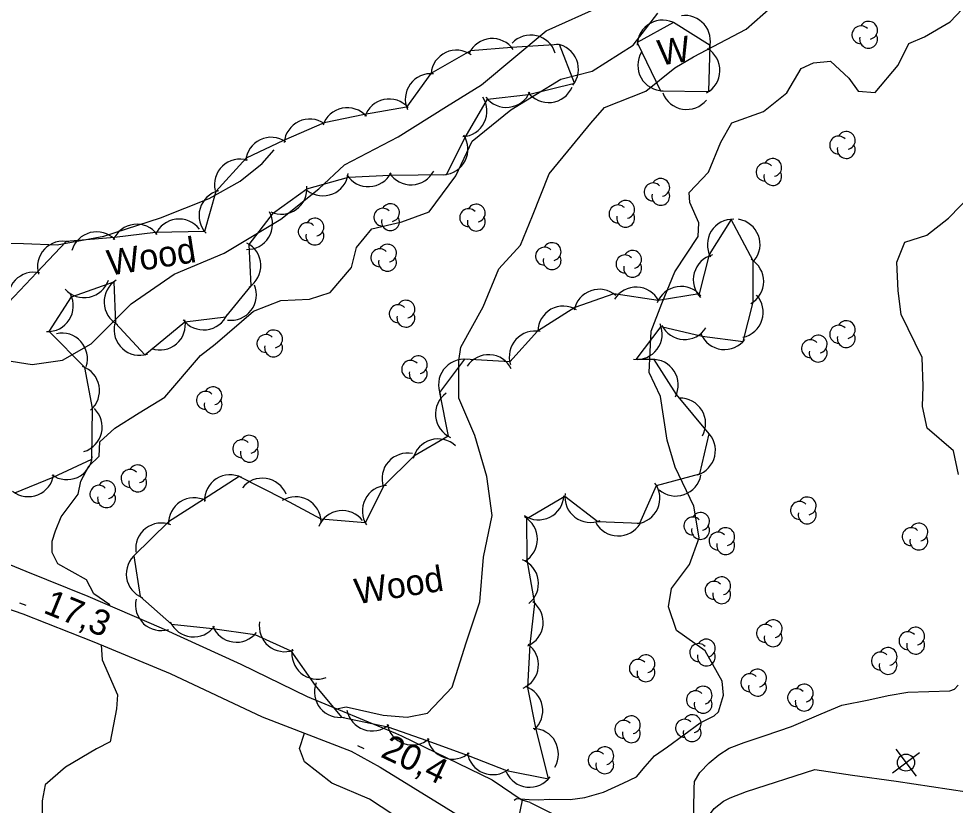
# Model space of a CAD drawing. Extents: x 646142 to 649934, y 5874075 to 5876351.
# Drawn here: x 647010.1 to 647120, y 5874901.2 to 5874993.5 of the extents above; entities that cross this region are included whole.
import ezdxf

# ---------------------------------------------------------------- set-up
doc = ezdxf.new("R2010")
doc.units = 0
for name, color, linetype in [('Niveau 1', 7, 'Continuous'), ('Niveau 19', 7, 'Continuous'), ('Niveau 2', 7, 'Continuous'), ('Niveau 3', 7, 'Continuous'), ('Niveau 36', 7, 'Continuous'), ('Niveau 4', 7, 'Continuous'), ('Niveau 44', 7, 'Continuous'), ('Niveau 52', 7, 'Continuous')]:
    doc.layers.add(name, color=color, linetype=linetype)

msp = doc.modelspace()

# ---------------------------------------------------------------- linework, layer by layer
at = {"layer": 'Niveau 1'}
for points in [[(647047.41, 5874912.5), (647048.53, 5874912.71), (647052.87, 5874911.75), (647055.68, 5874911.51), (647058.08, 5874911.98), (647060.97, 5874915.04), (647062.61, 5874920.22), (647064.23, 5874925.06), (647064.64, 5874930.3), (647065.68, 5874935.19), (647065.05, 5874939.75), (647063.65, 5874944.58), (647061.77, 5874948.95), (647061.75, 5874953.34), (647062, 5874954.92), (647064.61, 5874959.68), (647066.44, 5874964.13), (647069.01, 5874966.92), (647070.41, 5874970.35), (647072.37, 5874975.27), (647075.12, 5874978.6), (647077.24, 5874981.23), (647078.86, 5874983.07), (647083.72, 5874984.99), (647087.11, 5874987.74), (647089.31, 5874989), (647095.49, 5874992.26), (647098.42, 5874994.86)], [(647062.19, 5874853.88), (647063.16, 5874855.88), (647062.71, 5874856.94), (647061.06, 5874857.7), (647059.61, 5874860.1), (647058.71, 5874862.15), (647056.52, 5874864.37), (647056.19, 5874865.95), (647056.75, 5874868.55), (647057.24, 5874872.42), (647056.15, 5874875.84), (647054.13, 5874878.64), (647053.57, 5874880.79), (647053.96, 5874883.43), (647054, 5874888.29), (647054.75, 5874891.89), (647056.92, 5874895.91), (647057.02, 5874897.25), (647055.38, 5874899.17), (647051.28, 5874901.89), (647046.85, 5874903.76), (647043.64, 5874906.28), (647043.08, 5874907.84), (647043.63, 5874909.64)]]:
    msp.add_lwpolyline(points, dxfattribs=at)
at = {"layer": 'Niveau 19'}
for points in [[(646956.64, 5874982.64), (646957.27, 5874973.6), (646958.12, 5874968.89), (646958.69, 5874963.46), (646959.08, 5874961.51), (646960.28, 5874959.62), (646963.28, 5874955.54), (646968.34, 5874950.23), (646973.77, 5874946.12), (646979.55, 5874941.91), (646985.8, 5874939.02), (646993.5, 5874935.43), (647000.66, 5874932.62), (647004.71, 5874931.19), (647010.93, 5874928.65), (647018.21, 5874925.73), (647026.82, 5874921.99), (647036.17, 5874917.73), (647043.97, 5874913.93), (647054.34, 5874909.64), (647055.05, 5874909.32), (647065.67, 5874904.14), (647069.18, 5874901.78)], [(646938.02, 5874920.39), (646945.32, 5874923.5), (646951.28, 5874926.75), (646958.94, 5874929.59), (646963.33, 5874931.22), (646969.44, 5874933.03), (646979.24, 5874933.97), (646982.52, 5874934.12), (646984.51, 5874933.75), (646985.91, 5874933.31), (646990.94, 5874930.74), (646995.74, 5874928.53), (647002.07, 5874926.12), (647005.59, 5874925.34), (647010.58, 5874923.64), (647018.93, 5874920.34), (647027.89, 5874916.63), (647038.67, 5874911.56), (647049.14, 5874907.5), (647052.53, 5874905.64), (647068.02, 5874896.1)]]:
    msp.add_lwpolyline(points, dxfattribs=at)
at = {"layer": 'Niveau 2'}
for points in [[(647008.48, 5874953.4), (647011.67, 5874952.9), (647015.23, 5874953.43), (647018.6, 5874955.33), (647023.32, 5874960.02), (647028.34, 5874963.52), (647034.22, 5874965.96), (647040.87, 5874969.97), (647045.35, 5874973.54), (647048.34, 5874976.32), (647054.66, 5874979.61), (647060.31, 5874983.18), (647064.42, 5874985.72), (647072.01, 5874992.08), (647078.48, 5874994.98), (647085.23, 5874998.54), (647090.86, 5875001.06), (647095.93, 5875004.05), (647102.07, 5875006.74), (647108.2, 5875008.27), (647114.93, 5875011.48), (647118.07, 5875014.51)], [(647068.26, 5874901.76), (647068.52, 5874901.97), (647070.03, 5874901.84), (647071.1, 5874901.8), (647072.4, 5874901.89), (647074.81, 5874901.86), (647076.53, 5874902.09), (647078.73, 5874902.71), (647081.04, 5874903.77), (647082.6, 5874904.51), (647083.63, 5874905.73), (647084.71, 5874906.96), (647086.24, 5874908.04), (647090.09, 5874910.86), (647091.74, 5874911.66), (647092.22, 5874912.15), (647092.82, 5874914.08), (647092.66, 5874915.73), (647090.69, 5874919.29), (647087.32, 5874921.67), (647086.35, 5874924.45), (647086.72, 5874926.62), (647088.82, 5874929.43), (647089.96, 5874932.54), (647089.36, 5874936.28), (647087.17, 5874940.85), (647086.22, 5874944.04), (647085.43, 5874949.15), (647084.11, 5874951.96), (647084.33, 5874956.82), (647085.58, 5874960.06), (647087.12, 5874963.78), (647089.85, 5874967.91), (647089.92, 5874969.53), (647088.87, 5874971.9), (647088.81, 5874973.11), (647091.07, 5874975.46), (647092.52, 5874979), (647093.81, 5874981.26), (647097.5, 5874982.6), (647100.24, 5874984.78), (647101.93, 5874987.65), (647103.37, 5874988.31), (647105.38, 5874988.51), (647107.55, 5874986.53), (647108.63, 5874984.97), (647110.61, 5874984.82), (647113.31, 5874988.03), (647114.57, 5874990.57), (647116.4, 5874991.38), (647119.42, 5874993.12), (647122.93, 5874996.86)], [(647020.78, 5874924.61), (647020.8, 5874924.68), (647018.92, 5874925.99), (647018.07, 5874927.64), (647014.69, 5874929.51), (647014.03, 5874930.83), (647014.02, 5874932.16), (647014.43, 5874933.36), (647015.08, 5874935.04), (647017.09, 5874937.67), (647017.41, 5874939.2), (647018.34, 5874940.97), (647019.56, 5874942.13), (647019.63, 5874943.82), (647021.39, 5874945.43), (647024.24, 5874947.22), (647027.26, 5874949.08), (647031.44, 5874953.94), (647033.17, 5874955.27), (647037.67, 5874959.18), (647040.86, 5874960.42), (647044.22, 5874960.58), (647046.65, 5874961.34), (647049.15, 5874964.3), (647049.74, 5874966.62), (647051.56, 5874968.82), (647055.08, 5874969.63), (647058.28, 5874970.81), (647061.41, 5874975.05), (647063.34, 5874979.11), (647067.86, 5874982.79), (647073.73, 5874986.38), (647077.42, 5874987.32), (647082.23, 5874990.39), (647085.12, 5874994.14)], [(647120.39, 5874939.98), (647119.83, 5874942.75), (647116.72, 5874945.43), (647116.18, 5874947.97), (647116.24, 5874950.34), (647116.14, 5874953.72), (647113.67, 5874958.77), (647113.34, 5874961.56), (647113.18, 5874964.93), (647114.11, 5874967.27), (647116.69, 5874968.1), (647119.21, 5874970.07), (647123.36, 5874974.34)], [(647019.79, 5874919.99), (647019.91, 5874918.23), (647021.71, 5874914.12), (647021.58, 5874912.49), (647020.85, 5874908.6), (647019.24, 5874907.8), (647015.61, 5874905.65), (647013.2, 5874903.56), (647012.86, 5874901.68), (647012.88, 5874899.02)], [(647090.87, 5874896.34), (647089.8, 5874896.81), (647089.51, 5874897.35), (647089.35, 5874898.4), (647089.34, 5874900.76), (647089.37, 5874903.13), (647089.43, 5874903.96), (647090.04, 5874905.03), (647091.13, 5874906.16), (647092.28, 5874907.1), (647093.5, 5874907.86), (647095.26, 5874908.53), (647097.73, 5874909.37), (647100.8, 5874910.41), (647104.27, 5874911.89), (647106.71, 5874912.92), (647109.88, 5874913.54), (647112.14, 5874914.07), (647114.46, 5874914.46), (647119.37, 5874914.59), (647119.92, 5874914.79), (647120.36, 5874915.27)]]:
    msp.add_lwpolyline(points, dxfattribs=at)
at = {"layer": 'Niveau 3'}
for p, q in [((647010.22, 5874924.94), (647010.96, 5874924.64)), ((647049.88, 5874908.18), (647050.6, 5874907.83))]:
    msp.add_line(p, q, dxfattribs=at)
at = {"layer": 'Niveau 36'}
for p, q in [((647113.03, 5874907.77), (647115.43, 5874904.58)), ((647112.64, 5874904.98), (647115.83, 5874907.37))]:
    msp.add_line(p, q, dxfattribs=at)
msp.add_circle((647114.24, 5874906.17), 1, dxfattribs=at)
at = {"layer": 'Niveau 4'}
msp.add_lwpolyline([(646977.28, 5874967.68), (646980.23, 5874968.49), (646982.34, 5874968.18), (646984.21, 5874966.58), (646985.87, 5874966.13), (646990.46, 5874966.6), (646999.03, 5874967.96), (647004.2, 5874968.47), (647007.08, 5874967.18), (647010.68, 5874967.11), (647014.63, 5874966.95), (647020.1, 5874967.96), (647026.75, 5874970.1), (647032.45, 5874972.4), (647036.1, 5874974.43), (647038.7, 5874976.49), (647040.07, 5874978.11)], dxfattribs=at)
at = {"layer": 'Niveau 44'}
for points in [[(647086.95, 5874993.04), (647082.71, 5874990.68), (647085.42, 5874985.04), (647091.1, 5874984.94), (647091.24, 5874990.34), (647086.95, 5874993.04)], [(647013.7, 5874956.77), (647016.32, 5874960.85), (647021.28, 5874962.6), (647021.45, 5874957.75), (647024.91, 5874954.04), (647029.61, 5874957.92), (647034.43, 5874958.5), (647037.4, 5874962.15), (647037.16, 5874967), (647040, 5874970.69), (647043.94, 5874973.52), (647048.8, 5874974.91), (647053.65, 5874975.12), (647060.31, 5874975.21), (647062.49, 5874979.55), (647065.13, 5874984.04), (647069.95, 5874984.6), (647075.33, 5874985.93), (647073.56, 5874990.45), (647067.96, 5874990.12), (647063.12, 5874989.72), (647058.48, 5874987.04), (647055.63, 5874983.11), (647050.69, 5874982.26), (647045.94, 5874981.27), (647041.18, 5874979.2), (647036.79, 5874977.12), (647033.26, 5874973.19), (647031.9, 5874968.53), (647026.16, 5874968.41), (647021.35, 5874967.81), (647015.69, 5874967.34), (647012.25, 5874963.71), (647008.92, 5874960.18)], [(647082.58, 5874953.49), (647085.49, 5874957.38), (647090.32, 5874956.21), (647095.14, 5874955.62), (647096.29, 5874960.23), (647096.31, 5874965.08), (647093.72, 5874969.94), (647091.15, 5874965.82), (647089.96, 5874961.18), (647085.17, 5874960.42), (647079.96, 5874961.2), (647075.38, 5874959.58), (647071.01, 5874956.81), (647067.74, 5874953.22), (647062.41, 5874953.51), (647059.51, 5874949.62), (647060.5, 5874944.49), (647056.48, 5874942.15), (647052.96, 5874938.67), (647050.77, 5874934.33), (647045.59, 5874934.76), (647041.32, 5874937.07), (647036, 5874939.75), (647031.79, 5874937.06), (647027.7, 5874934.44), (647023.63, 5874930.46), (647024.35, 5874925.66), (647028.05, 5874922.43), (647032.87, 5874921.92), (647037.81, 5874921.2), (647042.06, 5874919.28), (647044.91, 5874915.23), (647048, 5874911.49), (647053.43, 5874910.37), (647058.02, 5874908.77), (647062.84, 5874907), (647067.35, 5874905.23), (647072.29, 5874904.27), (647070.81, 5874910.24), (647069.87, 5874915), (647070.15, 5874920.02), (647070.68, 5874924.85), (647069.77, 5874929.98), (647069.75, 5874934.84), (647074.2, 5874937.43), (647078.07, 5874934.49), (647082.99, 5874934.28), (647084.95, 5874938.71), (647090.05, 5874940.05), (647091.13, 5874944.78), (647087.3, 5874949.4), (647084.69, 5874953.49), (647082.58, 5874953.49)], [(647009.65, 5874937.85), (647014.15, 5874939.68), (647018.69, 5874941.79), (647018.76, 5874947.78), (647017.88, 5874952.55), (647013.7, 5874956.77)]]:
    msp.add_lwpolyline(points, dxfattribs=at)
for centre, radius, start, end in [((647085.69, 5874990.32), 3, 59.1526, 179.1306), ((647088.29, 5874990.87), 3, 343.847, 97.7618), ((647109.85, 5874992.13), 1.05, 282.2692, 149.7263), ((647108.95, 5874991.6), 1.05, 44.1154, 269.804), ((647065.68, 5874988.16), 3, 34.688, 154.666), ((647070.21, 5874988.57), 3, 17.3454, 137.3233), ((647109.85, 5874991.08), 1.05, 166.9369, 29.6212), ((647072.8, 5874987.55), 3, 321.3512, 81.3291), ((647089.4, 5874987.41), 3, 298.6443, 58.6222), ((647061.49, 5874986.8), 3, 54.7762, 174.7542), ((647085.77, 5874988.02), 3, 149.4137, 269.3917), ((647058.48, 5874984.04), 3, 84.0284, 204.0064), ((647072.3, 5874986.65), 3, 216.6504, 336.6284), ((647067.34, 5874986.08), 3, 216.6504, 336.6284), ((647088.5, 5874985.84), 3, 200.8305, 320.8084), ((647053.57, 5874981.06), 3, 41.7661, 161.7441), ((647062.07, 5874982.64), 3, 273.3404, 33.3183), ((647048.67, 5874980.04), 3, 41.7661, 161.7441), ((647044.26, 5874978.71), 3, 55.341, 175.319), ((647107.23, 5874979.19), 1.05, 282.2692, 149.7263), ((647039.74, 5874976.57), 3, 55.341, 175.319), ((647059.83, 5874978.17), 3, 273.3404, 33.3183), ((647106.33, 5874978.66), 1.05, 44.1154, 269.804), ((647107.23, 5874978.14), 1.05, 166.9369, 29.6212), ((647036.08, 5874974), 3, 73.21, 193.188), ((647098.6, 5874976.02), 1.05, 282.2692, 149.7263), ((647056.15, 5874976.99), 3, 212.474, 332.452), ((647097.7, 5874975.49), 1.05, 44.1154, 269.804), ((647045.81, 5874975.7), 3, 232.4474, 352.4253), ((647051.15, 5874976.78), 3, 212.474, 332.452), ((647085.46, 5874973.69), 1.05, 282.2692, 149.7263), ((647098.6, 5874974.97), 1.05, 166.9369, 29.6212), ((647040.94, 5874973.54), 3, 245.6661, 5.6441), ((647084.56, 5874973.16), 1.05, 44.1154, 269.804), ((647034.27, 5874970.37), 3, 103.6801, 223.658), ((647085.46, 5874972.64), 1.05, 166.9369, 29.6212), ((647052.84, 5874970.19), 1.05, 44.1154, 269.804), ((647053.74, 5874970.72), 1.05, 282.2692, 149.7263), ((647062.91, 5874970.14), 1.05, 44.1154, 269.804), ((647063.81, 5874970.67), 1.05, 282.2692, 149.7263), ((647080.44, 5874970.58), 1.05, 44.1154, 269.804), ((647081.34, 5874971.11), 1.05, 282.2692, 149.7263), ((647036.91, 5874969.41), 3, 268.4171, 28.395), ((647044.87, 5874969.03), 1.05, 282.2692, 149.7263), ((647053.74, 5874969.67), 1.05, 166.9369, 29.6212), ((647063.81, 5874969.62), 1.05, 166.9369, 29.6212), ((647081.34, 5874970.06), 1.05, 166.9369, 29.6212), ((647023.97, 5874966.36), 3, 37.0913, 157.0693), ((647028.93, 5874966.98), 3, 37.0913, 157.0693), ((647043.97, 5874968.5), 1.05, 44.1154, 269.804), ((647093.93, 5874966.95), 3, 87.9469, 207.9248), ((647094.11, 5874966.99), 3, 320.7578, 80.7358), ((647019.25, 5874965.47), 3, 44.2853, 164.2632), ((647044.87, 5874967.98), 1.05, 166.9369, 29.6212), ((647015.3, 5874964.37), 3, 76.6373, 196.6153), ((647035.52, 5874964.49), 3, 302.7924, 62.7704), ((647053.39, 5874965.96), 1.05, 282.2692, 149.7263), ((647072.71, 5874966.15), 1.05, 282.2692, 149.7263), ((647052.49, 5874965.43), 1.05, 44.1154, 269.804), ((647071.81, 5874965.62), 1.05, 44.1154, 269.804), ((647081.26, 5874964.71), 1.05, 44.1154, 269.804), ((647082.16, 5874965.24), 1.05, 282.2692, 149.7263), ((647092.28, 5874962.85), 3, 104.397, 224.3749), ((647053.39, 5874964.91), 1.05, 166.9369, 29.6212), ((647072.71, 5874965.1), 1.05, 166.9369, 29.6212), ((647082.16, 5874964.19), 1.05, 166.9369, 29.6212), ((647094.54, 5874962.66), 3, 299.7556, 59.7335), ((647011.87, 5874960.73), 3, 76.6373, 196.6153), ((647017.78, 5874963.75), 3, 221.9676, 341.9456), ((647023.13, 5874960.24), 3, 121.9925, 241.9704), ((647035.01, 5874961.09), 3, 262.425, 22.4029), ((647078.25, 5874958.73), 3, 49.4299, 169.4078), ((647082.57, 5874958.98), 3, 27.8096, 147.7875), ((647087.84, 5874959.06), 3, 39.0131, 158.991), ((647013.52, 5874959.77), 3, 267.2843, 27.2623), ((647055.55, 5874959.39), 1.05, 282.2692, 149.7263), ((647094.48, 5874959.03), 3, 282.0603, 42.0382), ((647054.65, 5874958.86), 1.05, 44.1154, 269.804), ((647074.04, 5874956.76), 3, 59.2123, 179.1902), ((647026.67, 5874957.6), 3, 250.8363, 10.8143), ((647031.81, 5874959.96), 3, 216.8062, 336.7841), ((647055.55, 5874958.34), 1.05, 166.9369, 29.6212), ((647107.23, 5874956.99), 1.05, 282.2692, 149.7263), ((647024.3, 5874956.98), 3, 167.6236, 287.6016), ((647040.02, 5874955.9), 1.05, 282.2692, 149.7263), ((647082.63, 5874956.49), 3, 263.1968, 23.1748), ((647088.25, 5874958.84), 3, 206.6835, 326.6614), ((647106.33, 5874956.46), 1.05, 44.1154, 269.804), ((647015.18, 5874953.59), 3, 342.3128, 102.2907), ((647039.12, 5874955.37), 1.05, 44.1154, 269.804), ((647070.68, 5874953.83), 3, 77.6559, 197.6339), ((647092.94, 5874957.66), 3, 203.0472, 323.0251), ((647103.04, 5874954.76), 1.05, 44.1154, 269.804), ((647103.94, 5874955.29), 1.05, 282.2692, 149.7263), ((647107.23, 5874955.94), 1.05, 166.9369, 29.6212), ((647040.02, 5874954.85), 1.05, 166.9369, 29.6212), ((647103.94, 5874954.24), 1.05, 166.9369, 29.6212), ((647057, 5874952.86), 1.05, 282.2692, 149.7263), ((647065.24, 5874951.06), 3, 26.5898, 146.5677), ((647016.59, 5874949.84), 3, 310.4626, 70.4405), ((647056.1, 5874952.33), 1.05, 44.1154, 269.804), ((647062.38, 5874950.51), 3, 83.35, 203.328), ((647084.51, 5874950.5), 3, 332.629, 92.607), ((647057, 5874951.81), 1.05, 166.9369, 29.6212), ((647032.92, 5874949.23), 1.05, 282.2692, 149.7263), ((647032.02, 5874948.7), 1.05, 44.1154, 269.804), ((647062.02, 5874947.08), 3, 125.6182, 245.5961), ((647032.92, 5874948.18), 1.05, 166.9369, 29.6212), ((647087.73, 5874945.96), 3, 331.4926, 91.4705), ((647016.91, 5874945.57), 3, 286.2559, 46.2339), ((647088.87, 5874942.81), 3, 287.187, 47.165), ((647036.28, 5874943.01), 1.05, 44.1154, 269.804), ((647037.18, 5874943.54), 1.05, 282.2692, 149.7263), ((647059.32, 5874941.17), 3, 46.9258, 166.9037), ((647037.18, 5874942.49), 1.05, 166.9369, 29.6212), ((647015.76, 5874942.39), 3, 234.4054, 354.3834), ((647055.74, 5874939.5), 3, 78.3969, 198.3749), ((647023.17, 5874939.53), 1.05, 44.1154, 269.804), ((647024.07, 5874940.06), 1.05, 282.2692, 149.7263), ((647011.24, 5874940.39), 3, 232.1219, 352.0999), ((647024.07, 5874939.01), 1.05, 166.9369, 29.6212), ((647034.91, 5874936.96), 3, 62.5845, 182.5625), ((647038.71, 5874936.56), 3, 21.7085, 141.6864), ((647087.22, 5874940.46), 3, 229.3215, 349.2994), ((647019.52, 5874937.67), 1.05, 44.1154, 269.804), ((647020.42, 5874938.2), 1.05, 282.2692, 149.7263), ((647053.44, 5874935.71), 3, 93.2424, 213.2203), ((647082.36, 5874937.21), 3, 276.1362, 36.1141), ((647020.42, 5874937.15), 1.05, 166.9369, 29.6212), ((647030.69, 5874934.26), 3, 62.5845, 182.5625), ((647042.61, 5874934.37), 3, 1.4618, 121.4397), ((647071.1, 5874937.67), 3, 236.5909, 356.5688), ((647077.2, 5874937.37), 3, 172.731, 292.7089), ((647102.65, 5874936.3), 1.05, 282.2692, 149.7263), ((647101.75, 5874935.77), 1.05, 44.1154, 269.804), ((647048.09, 5874932.75), 3, 37.5033, 157.4812), ((647067.99, 5874932.4), 3, 300.2782, 60.2561), ((647089.23, 5874933.95), 1.05, 44.1154, 269.804), ((647090.13, 5874934.48), 1.05, 282.2692, 149.7263), ((647102.65, 5874935.25), 1.05, 166.9369, 29.6212), ((647026.84, 5874931.29), 3, 67.7198, 187.6977), ((647080.47, 5874935.78), 3, 208.6083, 328.5862), ((647090.13, 5874933.43), 1.05, 166.9369, 29.6212), ((647115.75, 5874933.23), 1.05, 282.2692, 149.7263), ((647092.18, 5874932.17), 1.05, 44.1154, 269.804), ((647093.08, 5874932.7), 1.05, 282.2692, 149.7263), ((647114.85, 5874932.7), 1.05, 44.1154, 269.804), ((647115.75, 5874932.18), 1.05, 166.9369, 29.6212), ((647093.08, 5874931.65), 1.05, 166.9369, 29.6212), ((647025.73, 5874928.32), 3, 128.544, 248.5219), ((647068.11, 5874927.2), 3, 308.3022, 68.2802), ((647091.71, 5874926.4), 1.05, 44.1154, 269.804), ((647092.61, 5874926.93), 1.05, 282.2692, 149.7263), ((647092.61, 5874925.88), 1.05, 166.9369, 29.6212), ((647026.82, 5874924.67), 3, 166.9765, 286.9545), ((647068.66, 5874922.63), 3, 293.7159, 53.6939), ((647098.65, 5874921.88), 1.05, 282.2692, 149.7263), ((647030.64, 5874923.93), 3, 204.0413, 324.0193), ((647035.67, 5874923.31), 3, 201.479, 321.4569), ((647041.34, 5874922.19), 3, 169.946, 289.9239), ((647097.75, 5874921.35), 1.05, 44.1154, 269.804), ((647115.37, 5874921.01), 1.05, 282.2692, 149.7263), ((647090.81, 5874919.62), 1.05, 282.2692, 149.7263), ((647098.65, 5874920.83), 1.05, 166.9369, 29.6212), ((647114.47, 5874920.48), 1.05, 44.1154, 269.804), ((647045.16, 5874918.97), 3, 169.946, 289.9239), ((647068.11, 5874917.66), 3, 293.7159, 53.6939), ((647089.91, 5874919.09), 1.05, 44.1154, 269.804), ((647112.14, 5874918.63), 1.05, 282.2692, 149.7263), ((647115.37, 5874919.96), 1.05, 166.9369, 29.6212), ((647083.72, 5874917.77), 1.05, 282.2692, 149.7263), ((647090.81, 5874918.57), 1.05, 166.9369, 29.6212), ((647111.24, 5874918.1), 1.05, 44.1154, 269.804), ((647082.82, 5874917.24), 1.05, 44.1154, 269.804), ((647112.14, 5874917.58), 1.05, 166.9369, 29.6212), ((647083.72, 5874916.72), 1.05, 166.9369, 29.6212), ((647095.91, 5874915.55), 1.05, 44.1154, 269.804), ((647096.81, 5874916.08), 1.05, 282.2692, 149.7263), ((647047.82, 5874914.48), 3, 159.4708, 279.4487), ((647068.61, 5874912.28), 3, 311.1464, 71.1244), ((647090.43, 5874914.08), 1.05, 282.2692, 149.7263), ((647096.81, 5874915.03), 1.05, 166.9369, 29.6212), ((647102.3, 5874914.33), 1.05, 282.2692, 149.7263), ((647089.53, 5874913.55), 1.05, 44.1154, 269.804), ((647101.4, 5874913.8), 1.05, 44.1154, 269.804), ((647090.43, 5874913.03), 1.05, 166.9369, 29.6212), ((647102.3, 5874913.28), 1.05, 166.9369, 29.6212), ((647051.58, 5874912.88), 3, 190.8476, 310.8255), ((647081.11, 5874910.08), 1.05, 44.1154, 269.804), ((647082.01, 5874910.61), 1.05, 282.2692, 149.7263), ((647088.25, 5874910.21), 1.05, 44.1154, 269.804), ((647089.15, 5874910.74), 1.05, 282.2692, 149.7263), ((647056.3, 5874911.24), 3, 190.8476, 310.8255), ((647070.45, 5874907.19), 3, 329.1778, 89.1557), ((647082.01, 5874909.56), 1.05, 166.9369, 29.6212), ((647089.15, 5874909.69), 1.05, 166.9369, 29.6212), ((647061.03, 5874909.59), 3, 190.8476, 310.8255), ((647077.99, 5874906.44), 1.05, 44.1154, 269.804), ((647078.89, 5874906.97), 1.05, 282.2692, 149.7263), ((647065.74, 5874907.76), 3, 188.5321, 308.51), ((647078.89, 5874905.92), 1.05, 166.9369, 29.6212), ((647070.07, 5874906.29), 3, 203.8397, 323.8176)]:
    msp.add_arc(centre, radius, start, end, dxfattribs=at)
at = {"layer": 'Niveau 52'}
for points in [[(647070.13, 5874901.49), (647081.09, 5874895.98), (647086.15, 5874894.29), (647088.91, 5874893.72), (647090.04, 5874897.36), (647090.61, 5874899.03), (647091.28, 5874900.21), (647091.73, 5874900.77), (647092.82, 5874901.63), (647093.6, 5874902.03), (647095.52, 5874902.78), (647103.56, 5874905.37), (647107.95, 5874904.72), (647113.09, 5874903.98), (647121.39, 5874902.76)], [(647070.13, 5874901.49), (647069.18, 5874901.78), (647068.02, 5874896.1), (647068.79, 5874895), (647069.33, 5874893.99), (647069.67, 5874893.08), (647069.78, 5874892.25), (647070.28, 5874885.52), (647070.58, 5874879.51), (647070.93, 5874873.03), (647071.44, 5874864.55), (647071.92, 5874857.83), (647072.2, 5874850.41)]]:
    msp.add_lwpolyline(points, dxfattribs=at)

# ---------------------------------------------------------------- texts
at = {"layer": 'Niveau 3'}
for s, rotation, p in [('17,3 ', 337.7697, (647012.87, 5874923.81)), ('20,4 ', 334.4842, (647052.46, 5874906.9))]:
    msp.add_text(s, height=3, rotation=rotation, dxfattribs=at).set_placement(p)
at = {"layer": 'Niveau 44'}
for s, p in [('W', (647085.35, 5874987.97)), ('Wood', (647020.73, 5874963.32)), ('Wood', (647049.77, 5874924.75))]:
    msp.add_text(s, height=3, rotation=8.9405, dxfattribs=at).set_placement(p)

doc.saveas('drawing.dxf')
